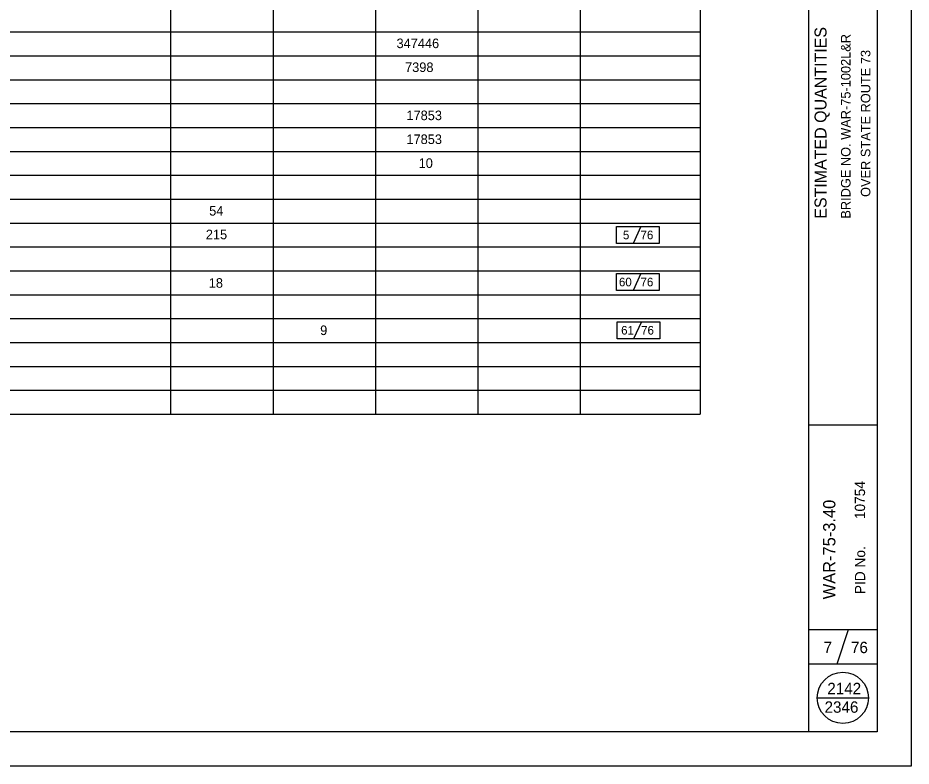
# Model space of a CAD drawing. Extents: x 0 to 34, y 0 to 22.
# Drawn here: x 20.91 to 34, y 0 to 10.96 of the extents above; entities that cross this region are included whole.
import ezdxf

# ---------------------------------------------------------------- set-up
doc = ezdxf.new("R2010")
doc.units = 0
for name, color, linetype in [('BR_P_Gen_Text', 7, 'Continuous'), ('BR_P_Sub_Text', 7, 'Continuous'), ('SH_Border', 7, 'Continuous'), ('SH_Cut_Line', 7, 'Continuous'), ('SH_Data', 7, 'Continuous'), ('SH_Text', 7, 'Continuous')]:
    doc.layers.add(name, color=color, linetype=linetype)

msp = doc.modelspace()

# ---------------------------------------------------------------- linework, layer by layer
at = {"layer": 'BR_P_Gen_Text'}
for p, q in [((30.04, 7.906), (29.925, 7.656)), ((30.04, 7.217), (29.925, 6.967)), ((30.049, 6.51), (29.933, 6.26))]:
    msp.add_line(p, q, dxfattribs=at)
for points in [[(29.683, 7.906), (30.309, 7.906), (30.309, 7.656), (29.683, 7.656)], [(29.683, 7.906), (30.309, 7.906), (30.309, 7.656), (29.683, 7.656)], [(29.683, 7.217), (30.309, 7.217), (30.309, 6.967), (29.683, 6.967)], [(29.683, 7.217), (30.309, 7.217), (30.309, 6.967), (29.683, 6.967)], [(29.692, 6.51), (30.318, 6.51), (30.318, 6.26), (29.692, 6.26)], [(29.692, 6.51), (30.318, 6.51), (30.318, 6.26), (29.692, 6.26)]]:
    msp.add_lwpolyline(points, close=True, dxfattribs=at)
at = {"layer": 'SH_Border'}
for p, q in [((32.5, 0.5), (32.5, 21.5)), ((32.5, 0.5), (32.5, 21.5)), ((32.5, 0.5), (32.5, 21.5)), ((32.5, 5), (33.5, 5)), ((32.5, 5), (33.5, 5)), ((32.5, 5), (33.5, 5)), ((32.5, 2), (33.5, 2)), ((32.917, 1.5), (33.083, 2)), ((32.5, 1.5), (33.5, 1.5))]:
    msp.add_line(p, q, dxfattribs=at)
msp.add_lwpolyline([(2, 21.5), (33.5, 21.5), (33.5, 0.5), (2, 0.5)], close=True, dxfattribs=at)
at = {"layer": 'SH_Cut_Line'}
msp.add_lwpolyline([(0, 22), (34, 22), (34, 0), (0, 0)], close=True, dxfattribs=at)
at = {"layer": 'SH_Data'}
msp.add_line((32.625, 1), (33.375, 1), dxfattribs=at)
msp.add_line((32.625, 1), (33.375, 1), dxfattribs=at)
msp.add_line((32.625, 1), (33.375, 1), dxfattribs=at)
msp.add_circle((33, 1), 0.375, dxfattribs=at)
at = {"layer": 'SH_Text'}
for p, q in [((30.91, 19.063), (30.91, 5.155)), ((23.15, 18.105), (23.15, 5.155)), ((24.65, 18.105), (24.65, 5.155)), ((26.15, 18.105), (26.15, 5.155)), ((27.65, 18.105), (27.65, 5.155)), ((29.15, 18.105), (29.15, 5.155)), ((3.59, 10.755), (30.91, 10.755)), ((3.59, 10.405), (30.91, 10.405)), ((3.59, 10.055), (30.91, 10.055)), ((3.59, 9.705), (30.91, 9.705)), ((3.59, 9.355), (30.91, 9.355)), ((3.59, 9.005), (30.91, 9.005)), ((3.59, 8.655), (30.91, 8.655)), ((3.59, 8.305), (30.91, 8.305)), ((3.59, 7.955), (30.91, 7.955)), ((3.59, 7.605), (30.91, 7.605)), ((3.59, 7.255), (30.91, 7.255)), ((3.59, 6.905), (30.91, 6.905)), ((3.59, 6.555), (30.91, 6.555)), ((3.59, 6.205), (30.91, 6.205)), ((3.59, 5.855), (30.91, 5.855)), ((3.59, 5.505), (30.91, 5.505)), ((3.59, 5.155), (30.91, 5.155))]:
    msp.add_line(p, q, dxfattribs=at)

# ---------------------------------------------------------------- texts
at = {"layer": 'BR_P_Gen_Text'}
for s, p in [(' 5', (29.731, 7.718)), ('76', (30.035, 7.718)), ('60', (29.719, 7.029)), ('76', (30.035, 7.029)), ('61', (29.751, 6.322)), ('76', (30.044, 6.322))]:
    msp.add_text(s, height=0.1259, dxfattribs=at).set_placement(p)
at = {"layer": 'BR_P_Sub_Text'}
msp.add_text('WAR-75-3.40', height=0.18, rotation=90, dxfattribs=at).set_placement((32.89, 2.444))
at = {"layer": 'SH_Data'}
for s, height, p in [('ESTIMATED QUANTITIES', 0.175, (32.76, 8.019)), ('BRIDGE NO. WAR-75-1002L&R', 0.14, (33.112, 8.02)), ('OVER STATE ROUTE 73', 0.14, (33.403, 8.338)), ('10754', 0.15, (33.325, 3.618)), ('PID No.', 0.15, (33.327, 2.519))]:
    msp.add_text(s, height=height, rotation=90, dxfattribs=at).set_placement(p)
for s, height, p in [('7', 0.167, (32.717, 1.655)), ('76', 0.1666, (33.119, 1.655)), ('2142', 0.1666, (32.772, 1.054)), ('2346', 0.1666, (32.732, 0.782))]:
    msp.add_text(s, height=height, dxfattribs=at).set_placement(p)
at = {"layer": 'SH_Text'}
for s, p in [('347446', (26.46, 10.518)), ('7398', (26.585, 10.168)), ('17853', (26.605, 9.463)), ('17853', (26.605, 9.113)), ('10', (26.784, 8.763)), ('54', (23.715, 8.065)), ('215', (23.666, 7.718)), ('18', (23.709, 7.008)), ('9', (25.341, 6.315))]:
    msp.add_text(s, height=0.14, dxfattribs=at).set_placement(p)

doc.saveas('drawing.dxf')
